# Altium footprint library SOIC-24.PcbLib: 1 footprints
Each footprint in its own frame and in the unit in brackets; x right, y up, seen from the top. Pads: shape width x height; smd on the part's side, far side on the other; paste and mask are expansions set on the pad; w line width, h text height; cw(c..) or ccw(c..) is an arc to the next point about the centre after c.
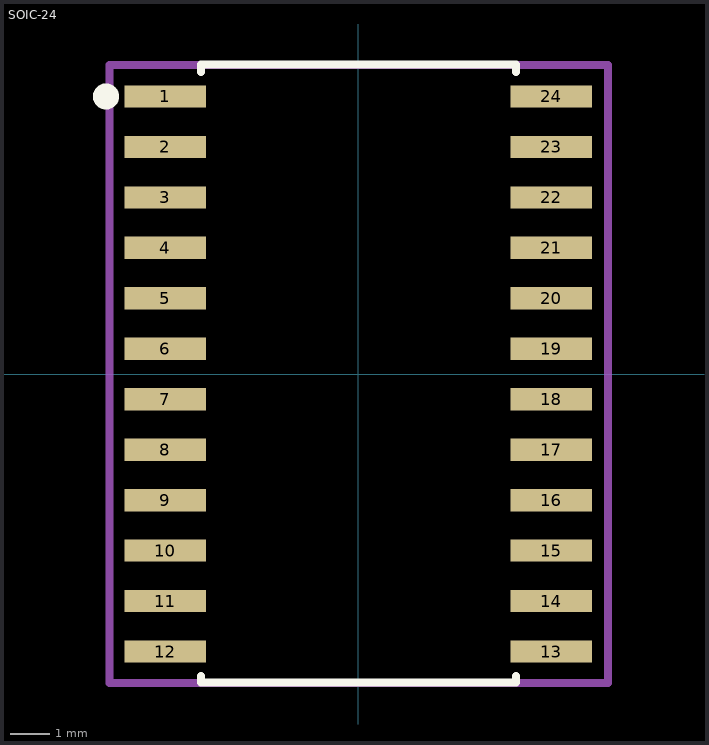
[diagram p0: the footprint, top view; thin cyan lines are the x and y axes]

## SOIC-24 [mil]
pads (24):
  rect 80.5x22 smd: 1(-191.25,275) 2(-191.25,225) 3(-191.25,175) 4(-191.25,125) 5(-191.25,75) 6(-191.25,25) 7(-191.25,-25) 8(-191.25,-75) 9(-191.25,-125) 10(-191.25,-175) 11(-191.25,-225) 12(-191.25,-275) 13(191.25,-275) 14(191.25,-225) 15(191.25,-175) 16(191.25,-125) 17(191.25,-75) 18(191.25,-25) 19(191.25,25) 20(191.25,75) 21(191.25,125) 22(191.25,175) 23(191.25,225) 24(191.25,275)
Top Overlay:
  circle w13.78: c-250,275 r6
  lines w7.87: -156,-299.1 -156,-305.83 156,-305.83 156,-299.1 ; -156,299.1 -156,306.5 156,306.5 156,299.1
Mechanical 15:
  lines w7.87: -246.7,-306 -246.7,306 -171,306 171,306 247.4,306 247.4,-306 171,-306 -171,-306 -246.7,-306
3D body "SOICW24_LB_ALM.step": height 104.09, standoff 0, extent -209.49,-307.01 209.49,307.01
